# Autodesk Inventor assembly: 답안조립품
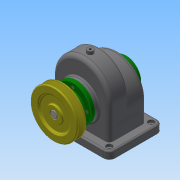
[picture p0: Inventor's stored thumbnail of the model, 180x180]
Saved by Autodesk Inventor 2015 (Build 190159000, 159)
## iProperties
Created: 2017-11
Part Number: 답안조립품
Document SubType Name: Assembly
Designer: user
Author: user
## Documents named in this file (13)
- C:\Users\user\Desktop\471107V1005\답안조립품.iam
- C:\Users\user\Desktop\471107V1005\본체.ipt
- C:\Users\user\Desktop\471107V1005\앞커버.ipt
- C:\Users\user\Desktop\471107V1005\뒤커버.ipt
- C:\Users\user\Desktop\471107V1005\오일 실 15 30 7.ipt
- C:\Users\user\Desktop\471107V1005\베어링 6002.ipt
- C:\Users\user\Desktop\471107V1005\축.ipt
- C:\Users\user\Desktop\471107V1005\키 - 6 x 6 x 22.ipt
- C:\Users\user\Desktop\471107V1005\키 - 5 x 5 x 18.ipt
- C:\Users\user\Desktop\471107V1005\V-벨트풀리.ipt
- C:\Users\user\Desktop\471107V1005\멈춤나사 - M4 x 10.ipt
- 멈춤나사 - M4 x 10.ipt
- C:\Users\user\Desktop\471107V1005\볼트 M3 x 8.ipt
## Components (1 placed, 1 different names)
1. V-벨트풀리:1
